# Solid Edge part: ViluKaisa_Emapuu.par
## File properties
Username: kaisa
Author: kaisa
Template: Iso Metric Part.par
Last saved by: kaisa
Revision: 5
Application: Solid Edge
Accuracy: 0.990
Face Style: Model Default
Fill Style: Normal
Coef. of Thermal Exp: 0.0
Thermal Conductivity: 0.0
Specific Heat: 0.0
Modulus of Elasticity: 0.0
Poisson's Ratio: 0.0
Yield Stress: 0.0
Ultimate Stress: 0.0
Elongation: 0.0
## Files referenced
C:\Users\kaisa\Documents\ViluKaisa_Parras.par
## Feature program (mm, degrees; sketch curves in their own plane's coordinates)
sketch for "unnamed Protrusion 1" plane through (0, 0, 0) normal (0, 1, 0) x-axis (-1, 0, 0)
  line (-147.3714, 75.1247) -> (-137.5892, 75.2317)
  bspline degree 3 poles (-135.1422, 55.1885) (-134.8765, 54.3588) (-134.7591, 53.8226) (-134.4921, 52.6621) (-134.3441, 52.0459) (-134.0441, 50.8585) (-133.8904, 50.2806) (-133.5669, 49.1147) (-133.3984, 48.5316) (-131.9972, 43.8824) (-130.5054, 40.0806) (-127.1778, 33.1627) (-125.3421, 30.0467) (-121.5508, 24.6534) (-119.6083, 22.4013) (-116.5878, 19.5626) (-115.4941, 18.6906) (-113.4284, 17.3177) (-112.4628, 16.8324) (-111.5666, 16.5036) knots 0 0.0288 0.0578 0.0871 0.1167 0.325 0.5333 0.7416 0.8683 1 multiplicities 4 2 2 2 2 2 2 2 2 4
  bspline degree 3 poles (-111.5666, 16.5036) (-111.4376, 16.4513) (-111.2961, 16.395) (-110.6373, 16.1362) (-110.0647, 15.9293) (-108.2546, 15.3283) (-106.9203, 14.9522) (-102.5452, 13.905) (-99.1607, 13.3244) (-87.8089, 11.9172) (-78.7057, 11.4354) (-58.5046, 11.015) (-47.4116, 11.0721) (-24.2225, 11.2948) (-12.1257, 11.4595) (12.1257, 11.4595) (24.2225, 11.2948) (47.4116, 11.0721) (58.5046, 11.015) (78.7057, 11.4354) (87.8089, 11.9172) (99.1607, 13.3244) (102.5452, 13.905) (106.9203, 14.9522) (108.2546, 15.3283) (109.7695, 15.8313) (110.0692, 15.9352) (110.358, 16.0395) knots 0 0.0039 0.0201 0.0525 0.1173 0.2468 0.3764 0.5059 0.6355 0.765 0.8946 0.9594 0.9917 1 multiplicities 4 2 2 2 2 2 2 2 2 2 2 2 2 4
  bspline degree 3 poles (110.358, 16.0395) (111.6417, 16.4484) (112.7578, 16.9609) (114.9853, 18.3133) (116.0972, 19.1506) (119.0151, 21.7921) (120.7989, 23.763) (124.3186, 28.4837) (126.0455, 31.2132) (129.2487, 37.2874) (130.7252, 40.6321) (132.2359, 44.8832) (132.4622, 45.5478) (132.8677, 46.7916) (133.0481, 47.366) (133.3973, 48.5262) (133.5673, 49.1155) (133.8917, 50.286) (134.0448, 50.8613) (134.3441, 52.0458) (134.4921, 52.6621) (134.7591, 53.8226) (134.8765, 54.3588) (135.0133, 55.0219) knots 0 0.1352 0.2653 0.4515 0.6377 0.8239 0.8579 0.8868 0.9155 0.9439 0.9721 1 multiplicities 4 2 2 2 2 2 2 2 2 2 2 4
  line (147.447, 75.2114) -> (137.6647, 75.3183)
  bspline degree 3 poles (144.8075, 53.0038) (146.2107, 58.258) (147.0654, 65.6316) (147.447, 75.2114) knots 0 1 multiplicities 4 4
  bspline degree 3 poles (144.8075, 53.0038) (144.6568, 52.2726) (144.52, 51.6474) (144.2225, 50.3546) (144.059, 49.6738) (143.7202, 48.3326) (143.5467, 47.6809) (143.1852, 46.3771) (142.9954, 45.7186) (142.6011, 44.4086) (142.3978, 43.7612) (141.943, 42.3664) (141.6886, 41.619) (138.5531, 32.7957) (134.7601, 25.7586) (128.4783, 17.3345) (126.2804, 14.8819) (120.8402, 9.954) (117.5302, 7.8584) (113.5969, 6.5774) knots 0 0.028 0.0563 0.0849 0.1137 0.1428 0.177 0.5513 0.7384 1 multiplicities 4 2 2 2 2 2 2 2 2 4
  bspline degree 3 poles (113.5969, 6.5774) (113.2737, 6.462) (112.9452, 6.349) (111.0924, 5.7339) (109.4844, 5.2835) (104.399, 4.0673) (100.6626, 3.4348) (88.4974, 1.9289) (79.1051, 1.4438) (58.5253, 1.0136) (47.3444, 1.0726) (24.0994, 1.2956) (12.0354, 1.4597) (-12.0354, 1.4597) (-24.0994, 1.2956) (-47.3444, 1.0726) (-58.5253, 1.0136) (-79.1051, 1.4438) (-88.4974, 1.9289) (-100.6626, 3.4348) (-104.399, 4.0673) (-109.4844, 5.2835) (-111.0924, 5.7339) (-113.3723, 6.4907) (-114.1098, 6.7565) (-114.9382, 7.0818) (-115.0648, 7.132) (-115.1916, 7.1829) knots 0 0.0071 0.0396 0.1045 0.2343 0.3641 0.494 0.6238 0.7536 0.8835 0.9484 0.9808 0.9971 1 multiplicities 4 2 2 2 2 2 2 2 2 2 2 2 2 4
  bspline degree 3 poles (-144.8075, 53.0038) (-144.6568, 52.2726) (-144.52, 51.6474) (-144.2225, 50.3546) (-144.059, 49.6737) (-143.7195, 48.3302) (-143.5455, 47.6758) (-143.1839, 46.3725) (-142.995, 45.7189) (-140.0448, 35.9307) (-136.0882, 27.9454) (-129.3939, 18.4241) (-127.0328, 15.6577) (-121.6058, 10.5567) (-118.5098, 8.4331) (-115.1916, 7.1829) knots 0 0.0289 0.0581 0.0876 0.1173 0.5359 0.7452 1 multiplicities 4 2 2 2 2 2 2 4
  bspline degree 3 poles (-144.8075, 53.0038) (-146.0266, 58.2063) (-146.8812, 65.58) (-147.3714, 75.1247) knots 0 1 multiplicities 4 4
extrude "unnamed Protrusion 1" add finite 10 along +normal
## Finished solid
Body 1: solid body, 14 faces, 36 edges, 24 vertices.
  Faces by surface: swept 10, plane 4
  Edges by curve: spline 20, line 16
Bounding box of the edges (mm; curved faces can reach further): 294.818 x 10.000 x 74.234, from (-147.447, 0, 1.0841) to (147.3714, 10, 75.3183).
Planar faces by outward normal: +y 1, -y 1, oblique 2
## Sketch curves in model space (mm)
spline (-113.5969, 0, 6.5774) -> (4.1582, 0, 1.4535) -> (115.1916, 0, 7.1829)
spline (-144.8075, 0, 53.0038) -> (-132.2701, 0, 22.5301) -> (-113.5969, 0, 6.5774)
spline (-144.8075, 0, 53.0038) -> (-146.5103, 0, 62.4855) -> (-147.447, 0, 75.2114)
line (-147.447, 0, 75.2114) -> (-137.6647, 0, 75.3183)
spline (-135.0133, 0, 55.0219) -> (-136.6461, 0, 64.3509) -> (-137.6647, 0, 75.3183)
spline (-110.358, 0, 16.0395) -> (-123.926, 0, 28.0424) -> (-135.0133, 0, 55.0219)
spline (111.5666, 0, 16.5036) -> (-0.8403, 0, 11.4593) -> (-110.358, 0, 16.0395)
spline (135.1422, 0, 55.1885) -> (124.3499, 0, 28.6743) -> (111.5666, 0, 16.5036)
spline (135.1422, 0, 55.1885) -> (136.6829, 0, 64.3609) -> (137.5892, 0, 75.2317)
line (147.3714, 0, 75.1247) -> (137.5892, 0, 75.2317)
spline (144.8075, 0, 53.0038) -> (146.3628, 0, 62.4359) -> (147.3714, 0, 75.1247)
spline (144.8075, 0, 53.0038) -> (132.7616, 0, 23.2663) -> (115.1916, 0, 7.1829)
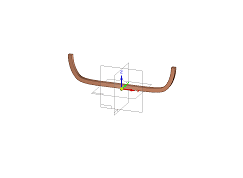
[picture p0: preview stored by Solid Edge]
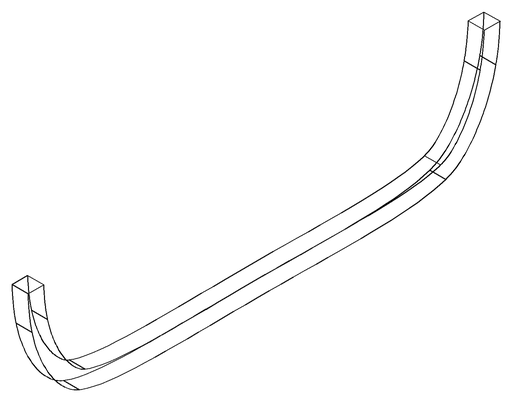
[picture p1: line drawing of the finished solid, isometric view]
